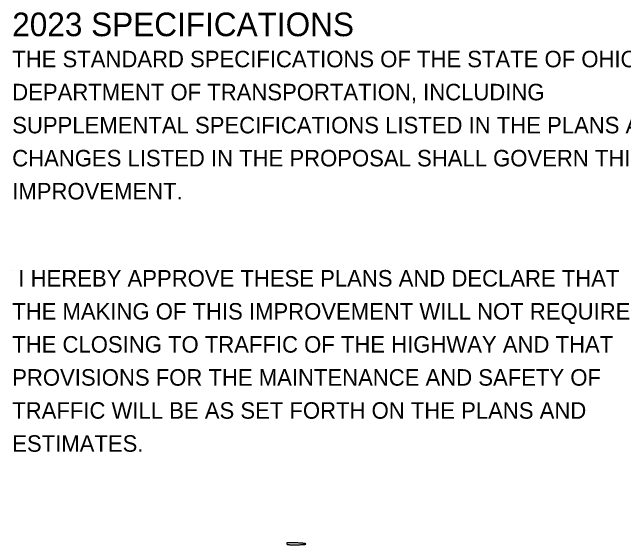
# Model space of a CAD drawing. Extents: x 0 to 34, y 0 to 22.
# Drawn here: x 24.53 to 29.71, y 5.78 to 10.3 of the extents above; entities that cross this region are included whole.
import ezdxf

# ---------------------------------------------------------------- set-up
doc = ezdxf.new("R2010")
doc.units = 0
doc.layers.add('SC_Scratch9', color=7, linetype='Continuous')
doc.layers.add('SH_Cut_Line', color=7, linetype='Continuous')

msp = doc.modelspace()

# ---------------------------------------------------------------- linework, layer by layer
at = {"layer": 'SC_Scratch9'}
for points in [[(26.9304, 5.7996), (26.8636, 5.8014), (26.8555, 5.8005), (26.8555, 5.7916)], [(26.8555, 5.7916), (26.8555, 5.7867), (26.8865, 5.7838), (26.9335, 5.7841)], [(26.9335, 5.7841), (27.0179, 5.7846), (27.0154, 5.7973), (26.9304, 5.7996)]]:
    msp.add_open_spline(points, degree=2, dxfattribs=at)
at = {"layer": 'SH_Cut_Line'}
msp.add_line((24.5279, 8.1122), (24.5279, 8.1122), dxfattribs=at)

# ---------------------------------------------------------------- texts
at = {"layer": 'SC_Scratch9'}
msp.add_text('2023 SPECIFICATIONS', height=0.2, dxfattribs=at).set_placement((24.5279, 10.0942))
at = {"layer": 'SH_Cut_Line'}
for s, p in [('THE STANDARD SPECIFICATIONS OF THE STATE OF OHIO, ', (24.5279, 9.8306)), ('DEPARTMENT OF TRANSPORTATION, INCLUDING ', (24.5279, 9.5506)), ('SUPPLEMENTAL SPECIFICATIONS LISTED IN THE PLANS AND ', (24.5279, 9.2706)), ('CHANGES LISTED IN THE PROPOSAL SHALL GOVERN THIS ', (24.5279, 8.9906)), ('IMPROVEMENT.', (24.5279, 8.7106)), (' I HEREBY APPROVE THESE PLANS AND DECLARE THAT', (24.5279, 7.9722)), ('THE MAKING OF THIS IMPROVEMENT WILL NOT REQUIRE', (24.5279, 7.6922)), ('THE CLOSING TO TRAFFIC OF THE HIGHWAY AND THAT', (24.5279, 7.4122)), ('PROVISIONS FOR THE MAINTENANCE AND SAFETY OF', (24.5279, 7.1322)), ('TRAFFIC WILL BE AS SET FORTH ON THE PLANS AND', (24.5279, 6.8522)), ('ESTIMATES.', (24.5279, 6.5722))]:
    msp.add_text(s, height=0.14, dxfattribs=at).set_placement(p)

doc.saveas('drawing.dxf')
